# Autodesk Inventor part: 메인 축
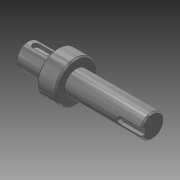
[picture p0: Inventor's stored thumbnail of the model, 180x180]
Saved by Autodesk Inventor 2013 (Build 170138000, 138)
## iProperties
Created: 2014-10
Part Number: 메인 축
Document SubType Name: Modeling
Designer: KYOUNG IL JANG
Density: 7.86 g/cm^3
Mass: 230.24 g
Surface Area: 74.3518 cm^2
Volume: 29.2926 cm^3
Material: 강철, 연강
Author: SeoGD™ [www.esajin.kr]
Revision Number: 1
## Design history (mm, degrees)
sketch "스케치1"
  geometry: L1 (10.497, -57.5)-(102.497, -57.5); L2 (10.497, -66)-(32.497, -66); L3 (32.497, -72.5)-(46.5, -72.5); L4 (46.5, -66)-(102.497, -66); L5 (102.497, -66)-(102.497, -57.5); L6 (10.497, -66)-(10.497, -57.5); L7 (46.5, -69.749)-(46.5, -45.251) reference; L8 (46.5, -72.5)-(46.5, -66); L9 (32.497, -72.5)-(32.497, -66); L10 (32.497, -35)-(32.497, -80) reference; 2 further points
  constraints: 16 end point, 2 parallel, 2 perpendicular, 2 point on line, 1 collinear, 1 horizontal, 1 midpoint
  dimensions: "d0" = 17 diameter of L4 L1; "d1" = 30 diameter of L3 L1; "d2" = 22 distance of L2.start L2.end; "d3" = 55.99692 distance of L4.start L4.end (derived); "d5" = 17 diameter of L2 L1; "d19" = 70 distance between parallel lines of L5 L9
revolve "회전1" sketch "스케치1" stored, may be unused: angle "d4" = 90 deg
chamfer "모따기1" distance "d6" = 1; stored, may be unused: second distance "d7" = 2, angle "d8" = 45 deg
node "작업 평면1"
sketch "스케치2"
  geometry: L1 (-11, -7.5)-(-11, 7.5) reference; L2 (-4.5, 2.5)-(4.5, 2.5); L3 (4.5, -2.5)-(-4.5, -2.5); A1 r 2.5 centre (4.5, 0) between (4.5, -2.5) and (4.5, 2.5); A2 r 2.5 centre (-4.5, 0) between (-4.5, 2.5) and (-4.5, -2.5); 2 further points
  constraints: 4 end point, 4 point on circle, 4 tangent, 2 centre point, 1 horizontal alignment, 1 midpoint, 1 parallel, 1 perpendicular
  dimensions: "d9" = 5 distance between parallel lines of L3 L2; "d10" = 14 dimension on A1 A2; "d11" = 4 distance edge to line of A2 L1
extrude "돌출1" cut sketch "스케치2" distance "d12" = 3; taper "d13" = 0 deg
node "작업 평면2"
sketch "스케치3"
  geometry: L1 (27.998, 7.5)-(27.998, -7.5) reference; L2 (27.998, 2.5)-(12.498, 2.5); L3 (12.498, -2.5)-(27.998, -2.5); A1 r 2.5 centre (12.498, 0) between (12.498, 2.5) and (12.498, -2.5); 2 further points
  constraints: 4 end point, 2 perpendicular, 2 point on circle, 2 point on line, 2 tangent, 1 centre point, 1 horizontal alignment, 1 midpoint
  dimensions: "d14" = 5 distance between parallel lines of L3 L2; "d15" = 18 dimension on A1 L1
extrude "돌출2" cut sketch "스케치3" distance "d16" = 3; taper "d17" = 0 deg
node "솔리드1"
node "참조4"
node "참조5"
